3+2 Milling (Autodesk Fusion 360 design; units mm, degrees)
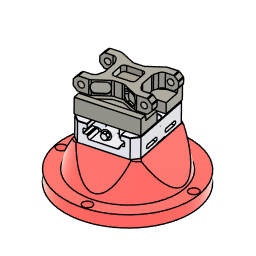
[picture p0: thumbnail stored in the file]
base_feature "Base Feature1"
base_feature "Base Feature1"
base_feature "Base Feature1"
base_feature "Base Feature1"
base_feature "Base Feature1"
as_built_joint "As-built1"
base_feature "Base Feature1"
step "RemoveFeatures"
sketch "Sketch1" plane through (0, 0, 0) normal (0, -1, 0) x axis (1, 0, 0)
  line L1 (35.56, 14.3539) -> (35.56, -14.3539)
  line L2 (40.4984, 27.6214) -> (36.4357, 18.4803)
  line L3 (65.1784, 33.655) -> (49.7827, 33.655)
  line L4 (65.1784, 49.53) -> (65.1784, 33.655)
  line L5 (45.4213, 49.53) -> (65.1784, 49.53)
  line L6 (12.4153, 32.9644) -> (41.2066, 48.4674)
  line L7 (-7.5985, 31.75) -> (7.5985, 31.75)
  line L8 (-41.2066, 48.4674) -> (-12.4153, 32.9644)
  line L9 (-65.1784, 49.53) -> (-45.4213, 49.53)
  line L10 (-65.1784, 33.655) -> (-65.1784, 49.53)
  line L11 (-49.7827, 33.655) -> (-65.1784, 33.655)
  line L12 (-36.4357, 18.4803) -> (-40.4984, 27.6214)
  line L13 (-35.56, -14.3539) -> (-35.56, 14.3539)
  line L14 (-40.4984, -27.6214) -> (-36.4357, -18.4803)
  line L15 (-65.1784, -33.655) -> (-49.7827, -33.655)
  line L16 (-65.1784, -49.53) -> (-65.1784, -33.655)
  line L17 (-45.4213, -49.53) -> (-65.1784, -49.53)
  line L18 (-12.4153, -32.9644) -> (-41.2066, -48.4674)
  line L19 (7.5985, -31.75) -> (-7.5985, -31.75)
  line L20 (41.2066, -48.4674) -> (12.4153, -32.9644)
  line L21 (65.1784, -49.53) -> (45.4213, -49.53)
  line L22 (65.1784, -33.655) -> (65.1784, -49.53)
  line L23 (49.7827, -33.655) -> (65.1784, -33.655)
  line L24 (36.4357, -18.4803) -> (40.4984, -27.6214)
  line L25 (-12.7, -12.7) -> (12.7, -12.7)
  line L26 (-12.7, 12.7) -> (-12.7, -12.7)
  line L27 (12.7, 12.7) -> (-12.7, 12.7)
  line L28 (12.7, -12.7) -> (12.7, 12.7)
  line L29 (-12.7, 12.7) -> (12.7, -12.7)
  line L30 (12.7, 12.7) -> (-12.7, -12.7)
  arc A1 centre (45.72, 14.3539) radius 10.16 clockwise from (35.56, 14.3539) to (36.4357, 18.4803)
  arc A2 centre (49.7827, 23.495) radius 10.16 clockwise from (40.4984, 27.6214) to (49.7827, 33.655)
  arc A3 centre (45.4213, 40.64) radius 8.89 clockwise from (41.2066, 48.4674) to (45.4213, 49.53)
  arc A4 centre (7.5985, 41.91) radius 10.16 clockwise from (12.4153, 32.9644) to (7.5985, 31.75)
  arc A5 centre (-7.5985, 41.91) radius 10.16 clockwise from (-7.5985, 31.75) to (-12.4153, 32.9644)
  arc A6 centre (-45.4213, 40.64) radius 8.89 clockwise from (-45.4213, 49.53) to (-41.2066, 48.4674)
  arc A7 centre (-49.7827, 23.495) radius 10.16 clockwise from (-49.7827, 33.655) to (-40.4984, 27.6214)
  arc A8 centre (-45.72, 14.3539) radius 10.16 clockwise from (-36.4357, 18.4803) to (-35.56, 14.3539)
  arc A9 centre (-45.72, -14.3539) radius 10.16 clockwise from (-35.56, -14.3539) to (-36.4357, -18.4803)
  arc A10 centre (-49.7827, -23.495) radius 10.16 clockwise from (-40.4984, -27.6214) to (-49.7827, -33.655)
  arc A11 centre (-45.4213, -40.64) radius 8.89 clockwise from (-41.2066, -48.4674) to (-45.4213, -49.53)
  arc A12 centre (-7.5985, -41.91) radius 10.16 clockwise from (-12.4153, -32.9644) to (-7.5985, -31.75)
  arc A13 centre (7.5985, -41.91) radius 10.16 clockwise from (7.5985, -31.75) to (12.4153, -32.9644)
  arc A14 centre (45.4213, -40.64) radius 8.89 clockwise from (45.4213, -49.53) to (41.2066, -48.4674)
  arc A15 centre (49.7827, -23.495) radius 10.16 clockwise from (49.7827, -33.655) to (40.4984, -27.6214)
  arc A16 centre (45.72, -14.3539) radius 10.16 clockwise from (36.4357, -18.4803) to (35.56, -14.3539)
  point P62 (0, 0)
  point P1 (0, 0)
  point P60 (-12.7, 12.7)
  point P61 (12.7, 12.7)
  point P59 (-12.7, -12.7)
  horizontal L25
  perpendicular L25 L26
  parallel L25 L27
  parallel L26 L28
  coincident L29 P62
  coincident L30 P62
  coincident P1 P62
  dimension "d1" distance P60 P61 = 25.4
  dimension "d2" distance P59 P60 = 25.4
extrude "Extrude1" cut sketch "Sketch1" profile of L25 L26 L27 L28 against normal blind 3.175
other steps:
create_component "CreateComponent1"
create_component "CreateComponent1"
create_component "CreateComponent2"
create_component "CreateComponent3"
create_component "CreateComponent4"
create_component "CreateComponent5"
create_component "CreateComponent2"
